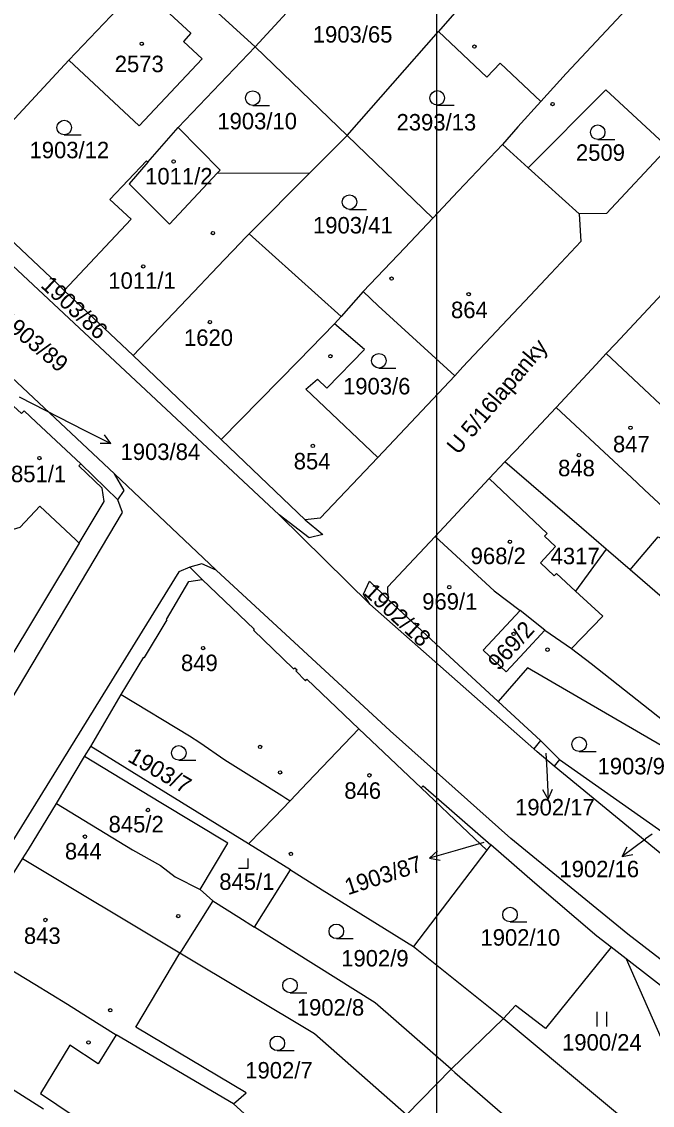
# Model space of a CAD drawing. Extents: x -667048 to -665920, y -1108425 to -1107247.
# Drawn here: x -666287.2 to -666222.1, y -1107598.2 to -1107486.3 of the extents above; entities that cross this region are included whole.
import ezdxf

# ---------------------------------------------------------------- set-up
doc = ezdxf.new("R2010")
doc.units = 0
for name, color, linetype in [('Default', 7, 'Continuous'), ('Hranice parcel', 7, 'Continuous'), ('Parcelní čísla', 7, 'Continuous'), ('Pop_ PČ_ popisy', 7, 'Continuous'), ('Vrstva 2', 7, 'Continuous'), ('Značky budov', 7, 'Continuous'), ('Značky kultur', 7, 'Continuous')]:
    doc.layers.add(name, color=color, linetype=linetype)

# ---------------------------------------------------------------- blocks, each defined once
blk = doc.blocks.new('3.041')
at = {"layer": 'Default'}
blk.add_line((8, 0), (1758, 0), dxfattribs=at)
blk.add_circle((8, 750), 750, dxfattribs=at)
blk = doc.blocks.new('3.191')
at = {"layer": 'Default'}
for p, q in [((-1000, 0), (0, 0)), ((0, 0), (0, 1000))]:
    blk.add_line(p, q, dxfattribs=at)
blk = doc.blocks.new('4.021')
at = {"layer": 'Default'}
blk.add_circle((-7, 1), 175, dxfattribs=at)
blk = doc.blocks.new('10291')
at = {"layer": 'Default'}
for p, q in [((0, 3001), (-500, 2001)), ((0, 1), (0, 3001)), ((0, 3001), (500, 2001))]:
    blk.add_line(p, q, dxfattribs=at)
blk = doc.blocks.new('3.061')
at = {"layer": 'Default'}
for p, q in [((-511, -1), (-511, 1499)), ((489, -1), (489, 1499))]:
    blk.add_line(p, q, dxfattribs=at)

msp = doc.modelspace()

# ---------------------------------------------------------------- linework, layer by layer
at = {"layer": 'Hranice parcel'}
for points in [[(-666252.55, -1107477.48), (-666263.1, -1107488.93)], [(-666263.1, -1107488.93), (-666272.69, -1107480.17)], [(-666223.24, -1107483.34), (-666231.01, -1107491.68), (-666233.61, -1107494.57)], [(-666275.81, -1107483.44), (-666273.98, -1107485.14), (-666273.19, -1107484.3), (-666269.71, -1107487.53), (-666270.49, -1107488.37), (-666268.55, -1107490.17), (-666275.07, -1107497.08), (-666282.3, -1107490.3)], [(-666282.3, -1107490.3), (-666275.81, -1107483.44)], [(-666242.51, -1107485.45), (-666244.17, -1107487.35)], [(-666253.6, -1107498.08), (-666244.17, -1107487.35)], [(-666244.17, -1107487.35), (-666239.2, -1107492.07), (-666237.81, -1107490.6), (-666233.61, -1107494.57)], [(-666263.1, -1107488.93), (-666271.03, -1107497.26)], [(-666253.6, -1107498.08), (-666263.1, -1107488.93)], [(-666293.44, -1107504.03), (-666293.52, -1107502.38), (-666282.3, -1107490.3)], [(-666234.91, -1107501.41), (-666226.9, -1107493.37), (-666220.49, -1107499.32)], [(-666233.61, -1107494.57), (-666235.97, -1107497.19), (-666237.58, -1107499)], [(-666274.15, -1107500.83), (-666271.03, -1107497.26)], [(-666271.03, -1107497.26), (-666266.7, -1107501.64), (-666267.01, -1107501.97)], [(-666257.44, -1107501.94), (-666253.6, -1107498.08)], [(-666244.76, -1107506.6), (-666253.6, -1107498.08)], [(-666237.58, -1107499), (-666242.14, -1107503.83), (-666244.76, -1107506.6)], [(-666234.91, -1107501.41), (-666237.58, -1107499)], [(-666220.49, -1107499.32), (-666226.85, -1107506.14), (-666229.64, -1107506.17)], [(-666278.09, -1107504.68), (-666274.3, -1107500.7), (-666274.15, -1107500.83)], [(-666274.15, -1107500.83), (-666276.1, -1107503.05), (-666271.94, -1107507.23), (-666267.01, -1107501.97)], [(-666267.01, -1107501.97), (-666257.44, -1107501.94)], [(-666257.44, -1107501.94), (-666263.69, -1107508.22)], [(-666229.64, -1107506.17), (-666234.91, -1107501.41)], [(-666260.6, -1107537.23), (-666295.55, -1107504.57)], [(-666293.44, -1107504.03), (-666283.56, -1107513.33), (-666282.79, -1107514.06)], [(-666282.79, -1107514.06), (-666275.87, -1107506.72), (-666278.09, -1107504.68)], [(-666244.76, -1107506.6), (-666247.65, -1107509.66), (-666251.94, -1107514.19)], [(-666229.64, -1107506.17), (-666229.49, -1107509.01), (-666232.58, -1107512.31), (-666234.7, -1107514.58), (-666241.65, -1107521.97), (-666242.47, -1107522.9)], [(-666263.69, -1107508.22), (-666264.11, -1107508.65), (-666264.6, -1107509.14)], [(-666254.23, -1107516.76), (-666263.69, -1107508.22)], [(-666264.6, -1107509.14), (-666266.24, -1107510.86), (-666267.6, -1107512.29), (-666268.77, -1107513.52), (-666275.69, -1107520.8)], [(-666226.87, -1107520.59), (-666225.92, -1107519.57), (-666219.66, -1107512.87), (-666216.46, -1107509.65)], [(-666277.6, -1107532.99), (-666300.51, -1107511.52)], [(-666275.69, -1107520.8), (-666282.79, -1107514.06)], [(-666251.94, -1107514.19), (-666254.23, -1107516.76)], [(-666251.94, -1107514.19), (-666250.4, -1107515.65), (-666242.47, -1107522.9)], [(-666254.89, -1107517.51), (-666254.23, -1107516.76)], [(-666254.89, -1107517.51), (-666258.62, -1107521.32), (-666266.58, -1107529.47)], [(-666250.44, -1107531.31), (-666256.59, -1107525.46), (-666257.86, -1107524.26), (-666256.66, -1107523.23), (-666255.71, -1107524.17), (-666251.82, -1107520.17), (-666254.89, -1107517.51)], [(-666275.69, -1107520.8), (-666268.07, -1107528.04), (-666266.58, -1107529.47)], [(-666232.04, -1107526.14), (-666227.91, -1107521.7), (-666226.87, -1107520.59)], [(-666217.35, -1107529.51), (-666226.87, -1107520.59)], [(-666242.47, -1107522.9), (-666250.44, -1107531.31)], [(-666289.33, -1107524.23), (-666289, -1107524.54), (-666289.28, -1107524.83), (-666287.19, -1107526.78), (-666286.92, -1107526.49), (-666285.69, -1107527.65), (-666281.08, -1107531.98)], [(-666237.31, -1107531.77), (-666236.19, -1107530.59), (-666232.04, -1107526.14)], [(-666232.04, -1107526.14), (-666225.6, -1107532.14), (-666224.29, -1107533.36)], [(-666266.58, -1107529.47), (-666263.36, -1107532.55), (-666257.93, -1107537.75)], [(-666250.44, -1107531.31), (-666256.38, -1107537.57), (-666257.93, -1107537.75)], [(-666281.24, -1107540.16), (-666278.66, -1107535.87), (-666278.86, -1107534.49), (-666281.28, -1107532.19), (-666281.08, -1107531.98)], [(-666281.08, -1107531.98), (-666277.25, -1107535.67)], [(-666238.94, -1107533.48), (-666237.31, -1107531.77)], [(-666226.88, -1107540.78), (-666229.41, -1107538.59), (-666237.31, -1107531.77)], [(-666277.6, -1107532.99), (-666267.1, -1107542.95)], [(-666277.25, -1107535.67), (-666276.6, -1107534.73), (-666277.6, -1107532.99)], [(-666244.53, -1107539.46), (-666238.94, -1107533.48)], [(-666232.09, -1107540.5), (-666233.22, -1107539.45), (-666232.96, -1107539.17), (-666238.94, -1107533.48)], [(-666224.29, -1107533.36), (-666222.9, -1107534.65), (-666219.57, -1107537.76), (-666218.32, -1107538.93), (-666216.68, -1107540.45)], [(-666338.35, -1107638.72), (-666322.57, -1107614), (-666276.79, -1107536.98), (-666277.25, -1107535.67)], [(-666302.26, -1107543.29), (-666299.12, -1107539.8), (-666294.21, -1107544.44), (-666293.01, -1107543.98), (-666289.29, -1107539.1), (-666287.32, -1107538.49), (-666285.31, -1107536.34), (-666281.6, -1107539.82), (-666281.24, -1107540.16)], [(-666260.6, -1107537.23), (-666251.27, -1107546.45)], [(-666257.93, -1107537.75), (-666256.11, -1107539.25), (-666257.5, -1107539.62), (-666260.6, -1107537.23)], [(-666281.24, -1107540.16), (-666289.12, -1107553.26)], [(-666249.35, -1107545.97), (-666249.41, -1107544.68), (-666244.53, -1107539.46)], [(-666244.53, -1107539.46), (-666238.43, -1107545.08), (-666235.74, -1107547.09)], [(-666224.4, -1107542.92), (-666221.52, -1107539.51), (-666217.33, -1107541.6), (-666204.54, -1107551.89)], [(-666232, -1107543.29), (-666232.22, -1107543.53), (-666233.66, -1107542.2), (-666232.09, -1107540.5)], [(-666226.88, -1107540.78), (-666230.03, -1107545.1)], [(-666224.4, -1107542.92), (-666226.88, -1107540.78)], [(-666267.1, -1107542.95), (-666268.6, -1107542.3), (-666269.82, -1107542.63)], [(-666269.82, -1107542.63), (-666270.97, -1107543.12), (-666317.97, -1107619.2), (-666330.09, -1107641.59)], [(-666268.54, -1107543.92), (-666269.82, -1107542.63)], [(-666176.16, -1107615.69), (-666192.08, -1107604.32), (-666208.42, -1107593.01), (-666224.62, -1107580.51), (-666236.71, -1107570.64), (-666249.16, -1107559.51), (-666267.1, -1107542.95)], [(-666230.03, -1107545.1), (-666232, -1107543.29)], [(-666208.38, -1107556.76), (-666224.4, -1107542.92)], [(-666276.92, -1107555.77), (-666274.56, -1107551.92), (-666274.49, -1107551.96), (-666272.18, -1107548.07), (-666272.25, -1107548.03), (-666269.92, -1107544.12), (-666268.54, -1107543.92)], [(-666268.54, -1107543.92), (-666263.18, -1107549.03), (-666263.27, -1107549.12), (-666260.23, -1107552.06), (-666259.12, -1107553.13), (-666259.01, -1107553.01), (-666258.77, -1107553.24), (-666258.88, -1107553.35), (-666257.89, -1107554.36), (-666257.75, -1107554.21), (-666252.38, -1107559.33)], [(-666251.27, -1107546.45), (-666251.91, -1107545.43), (-666251.29, -1107544.07), (-666249.35, -1107545.97)], [(-666238, -1107556.51), (-666243.92, -1107551.02), (-666249.35, -1107545.97)], [(-666230.03, -1107545.1), (-666227.23, -1107547.69)], [(-666234.35, -1107561.4), (-666251.27, -1107546.45)], [(-666235.74, -1107547.09), (-666239.57, -1107551.21), (-666237.18, -1107553.43)], [(-666233.19, -1107549.15), (-666235.74, -1107547.09)], [(-666227.23, -1107547.69), (-666230.46, -1107551.03)], [(-666237.18, -1107553.43), (-666235.3, -1107551.41), (-666233.19, -1107549.15)], [(-666233.19, -1107549.15), (-666230.46, -1107551.03)], [(-666230.46, -1107551.03), (-666228.42, -1107552.56), (-666215.48, -1107562.78)], [(-666216.1, -1107564.01), (-666234.98, -1107553.02), (-666238, -1107556.51)], [(-666280.06, -1107561.16), (-666276.92, -1107555.77)], [(-666276.92, -1107555.77), (-666269.86, -1107560.04), (-666268.81, -1107560.73), (-666266.21, -1107562.53), (-666262.93, -1107564.58), (-666260.35, -1107566.2), (-666259.91, -1107566.47), (-666259.48, -1107566.74)], [(-666238, -1107556.51), (-666233.66, -1107560.54)], [(-666252.38, -1107559.33), (-666257.68, -1107564.86), (-666259.48, -1107566.74)], [(-666252.38, -1107559.33), (-666245.97, -1107565.41)], [(-666280.7, -1107562.19), (-666280.06, -1107561.16)], [(-666263.76, -1107571.2), (-666272.32, -1107565.92), (-666280.06, -1107561.16)], [(-666233.66, -1107560.54), (-666234.35, -1107561.4)], [(-666232.22, -1107563.17), (-666234, -1107561.71), (-666234.35, -1107561.4)], [(-666233.66, -1107560.54), (-666231.68, -1107562.49)], [(-666283.59, -1107567.01), (-666280.7, -1107562.19)], [(-666268.78, -1107575.92), (-666265.9, -1107571.11), (-666272.81, -1107566.97), (-666280.7, -1107562.19)], [(-666231.68, -1107562.49), (-666232.22, -1107563.17)], [(-666231.68, -1107562.49), (-666219.63, -1107570.98)], [(-666220.53, -1107572.76), (-666232.22, -1107563.17)], [(-666245.97, -1107565.41), (-666245.77, -1107565.2), (-666238.76, -1107571.3)], [(-666239.19, -1107571.86), (-666241.1, -1107570.02), (-666245.97, -1107565.41)], [(-666287.09, -1107572.75), (-666286.47, -1107571.78), (-666283.59, -1107567.01)], [(-666283.59, -1107567.01), (-666275.73, -1107571.8)], [(-666259.48, -1107566.74), (-666261.11, -1107568.43), (-666263.76, -1107571.2)], [(-666259.43, -1107573.89), (-666263.76, -1107571.2)], [(-666238.76, -1107571.3), (-666239.19, -1107571.86)], [(-666234.22, -1107575.25), (-666238.76, -1107571.3)], [(-666292.44, -1107581.68), (-666290.01, -1107577.66), (-666290.08, -1107577.62), (-666288.07, -1107574.28), (-666287.09, -1107572.75)], [(-666270.85, -1107582.47), (-666287.09, -1107572.75)], [(-666275.73, -1107571.8), (-666272.87, -1107573.44), (-666271.35, -1107574.6)], [(-666239.19, -1107571.86), (-666246.74, -1107581.8)], [(-666263.16, -1107579.79), (-666259.43, -1107573.89)], [(-666259.43, -1107573.89), (-666257.86, -1107574.87), (-666256.17, -1107575.93), (-666246.74, -1107581.8)], [(-666271.35, -1107574.6), (-666268.78, -1107575.92)], [(-666268.78, -1107575.92), (-666267.47, -1107577.06)], [(-666226.34, -1107581.87), (-666227.84, -1107580.71), (-666234.22, -1107575.25)], [(-666267.47, -1107577.06), (-666270.73, -1107582.26), (-666270.85, -1107582.47)], [(-666267.47, -1107577.06), (-666264.77, -1107578.77), (-666263.16, -1107579.79)], [(-666242.87, -1107594.44), (-666250.71, -1107587.6), (-666263.16, -1107579.79)], [(-666292.44, -1107581.68), (-666285.82, -1107585.66), (-666282.46, -1107587.75), (-666280.38, -1107589.05), (-666277.42, -1107590.9)], [(-666265.33, -1107598.04), (-666264.01, -1107596.9), (-666275.39, -1107590.12), (-666270.85, -1107582.47)], [(-666247.46, -1107599.17), (-666256.95, -1107590.8), (-666270.85, -1107582.47)], [(-666246.74, -1107581.8), (-666237.45, -1107589.23)], [(-666226.34, -1107581.87), (-666233.14, -1107590.26)], [(-666224.8, -1107583.06), (-666226.34, -1107581.87)], [(-666210.49, -1107594.16), (-666224.8, -1107583.06)], [(-666224.8, -1107583.06), (-666217.14, -1107600.48)], [(-666233.14, -1107590.26), (-666236.23, -1107587.89), (-666237.45, -1107589.23)], [(-666237.45, -1107589.23), (-666242.87, -1107594.44)], [(-666237.45, -1107589.23), (-666237.08, -1107589.52), (-666219.88, -1107603.87)], [(-666284.93, -1107598.58), (-666288.23, -1107596.47), (-666297.89, -1107590.63)], [(-666277.42, -1107590.9), (-666279.29, -1107593.89), (-666282.21, -1107591.98), (-666285.23, -1107596.96)], [(-666265.33, -1107598.04), (-666277.42, -1107590.9)], [(-666242.87, -1107594.44), (-666247.46, -1107599.17)], [(-666242.87, -1107594.44), (-666242.48, -1107594.78), (-666202.56, -1107629.45), (-666159.85, -1107666.41)], [(-666285.23, -1107596.96), (-666273.33, -1107604.99), (-666273.91, -1107605.5)], [(-666256.08, -1107606.41), (-666265.33, -1107598.04)]]:
    msp.add_lwpolyline(points, dxfattribs=at)
at = {"layer": 'Pop_ PČ_ popisy'}
for points in [[(-666287.44, -1107525.05), (-666280.65, -1107528.51)], [(-666233.09, -1107561.84), (-666233.01, -1107563.59)], [(-666222.14, -1107570.19), (-666222.81, -1107570.69)], [(-666239.5, -1107571.06), (-666242.22, -1107571.83)]]:
    msp.add_lwpolyline(points, dxfattribs=at)
at = {"layer": 'Vrstva 2'}
msp.add_lwpolyline([(-666838.39, -1107343.37), (-666244.39, -1107343.37), (-666244.39, -1108183.37), (-666838.39, -1108183.37)], close=True, dxfattribs=at)

# ---------------------------------------------------------------- block references
at = {"layer": 'Pop_ PČ_ popisy'}
for p, xscale, yscale, rotation in [((-666280.65, -1107528.51), 0.001, 0.0010000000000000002, -117.00000000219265), ((-666233.01, -1107563.59), 0.0010000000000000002, 0.0010000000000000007, -177.0000000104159), ((-666222.81, -1107570.69), 0.001, 0.0010000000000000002, 127.00000002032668), ((-666242.22, -1107571.83), 0.0010000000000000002, 0.0010000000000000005, 105.9999999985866)]:
    msp.add_blockref('10291', p, dxfattribs=dict(at, xscale=xscale, yscale=yscale, rotation=rotation))
at = {"layer": 'Značky budov', "xscale": 0.0010000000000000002, "yscale": 0.0010000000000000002}
for p in [(-666274.78, -1107488.61), (-666240.46, -1107488.9), (-666232.39, -1107494.84), (-666271.5, -1107500.76), (-666267.44, -1107508.15), (-666274.63, -1107511.59), (-666249, -1107512.85), (-666241.05, -1107514.47), (-666267.75, -1107517.34), (-666255.32, -1107520.86), (-666224.35, -1107528.24), (-666257.13, -1107530.12), (-666285.34, -1107531.38), (-666229.67, -1107531.06), (-666236.8, -1107540.01), (-666243.06, -1107544.7), (-666236.42, -1107549.52), (-666268.45, -1107550.99), (-666232.92, -1107551.15), (-666262.57, -1107561.19), (-666260.51, -1107563.82), (-666251.29, -1107564.12), (-666274.15, -1107567.7), (-666280.65, -1107570.45), (-666259.39, -1107572.23), (-666284.72, -1107579.05), (-666271.02, -1107578.65), (-666278.03, -1107588.37), (-666280.28, -1107591.69)]:
    msp.add_blockref('4.021', p, dxfattribs=at)
at = {"layer": 'Značky kultur', "xscale": 0.0010000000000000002, "yscale": 0.0010000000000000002}
for name, p in [('3.041', (-666263.35, -1107494.97)), ('3.041', (-666244.31, -1107494.95)), ('3.041', (-666282.8, -1107498.01)), ('3.041', (-666227.75, -1107498.49)), ('3.041', (-666253.36, -1107505.7)), ('3.041', (-666250.33, -1107522.08)), ('3.041', (-666229.67, -1107561.66)), ('3.041', (-666270.98, -1107562.55)), ('3.191', (-666263.82, -1107573.7)), ('3.041', (-666236.8, -1107579.24)), ('3.041', (-666254.72, -1107580.97)), ('3.041', (-666259.5, -1107586.56)), ('3.061', (-666227.29, -1107590.04)), ('3.041', (-666260.81, -1107592.53))]:
    msp.add_blockref(name, p, dxfattribs=at)

# ---------------------------------------------------------------- texts
at = {"layer": 'Parcelní čísla'}
for s, p in [('1903/65', (-666257.14, -1107488.49)), ('2573', (-666277.58, -1107491.54)), ('1903/10', (-666266.99, -1107497.44)), ('2393/13', (-666248.5, -1107497.56)), ('1903/12', (-666286.37, -1107500.43)), ('2509', (-666229.99, -1107500.69)), ('1011/2', (-666274.44, -1107503.13)), ('1903/41', (-666257.12, -1107508.19)), ('1011/1', (-666278.24, -1107513.9)), ('864', (-666242.88, -1107516.93)), ('1620', (-666270.43, -1107519.79)), ('1903/6', (-666254.02, -1107524.8)), ('847', (-666226.17, -1107530.78)), ('1903/84', (-666276.98, -1107531.57)), ('854', (-666259.11, -1107532.54)), ('851/1', (-666288.28, -1107533.86)), ('848', (-666231.83, -1107533.25)), ('968/2', (-666240.85, -1107542.32)), ('4317', (-666232.6, -1107542.33)), ('969/1', (-666245.85, -1107547.02)), ('849', (-666270.74, -1107553.36)), ('1903/9', (-666227.76, -1107564.02)), ('846', (-666253.89, -1107566.54)), ('1902/17', (-666236.27, -1107568.26)), ('845/2', (-666278.21, -1107570.01)), ('844', (-666282.72, -1107572.8)), ('1902/16', (-666231.69, -1107574.64)), ('845/1', (-666266.79, -1107575.94)), ('843', (-666286.95, -1107581.52)), ('1902/10', (-666239.84, -1107581.7)), ('1902/9', (-666254.21, -1107583.85)), ('1902/8', (-666258.79, -1107588.92)), ('1900/24', (-666231.42, -1107592.53)), ('1902/7', (-666264.11, -1107595.41))]:
    msp.add_text(s, height=1.7, dxfattribs=at).set_placement(p)
for s, rotation, p in [('1903/86', 317, (-666285.31, -1107513.65)), ('1903/89', 320, (-666289.6, -1107517.34)), ('1902/18', 317, (-666251.97, -1107545.37)), ('969/2', 48, (-666237.97, -1107553.4)), ('1903/7', 330, (-666276.35, -1107562.62)), ('1903/87', 18, (-666253.52, -1107576.5))]:
    msp.add_text(s, height=1.7, rotation=rotation, dxfattribs=at).set_placement(p)
at = {"layer": 'Pop_ PČ_ popisy'}
msp.add_text('U 5/16lapanky', height=1.7, rotation=50, dxfattribs=at).set_placement((-666242.16, -1107531.11))

doc.saveas('drawing.dxf')
